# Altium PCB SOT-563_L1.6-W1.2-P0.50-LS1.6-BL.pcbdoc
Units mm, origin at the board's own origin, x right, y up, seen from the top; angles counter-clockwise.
Board outline 14.57 x 14.81 mm, 2 copper layers (Top Layer, Bottom Layer), stack 0 mm thick; 1 components, 0 nets, 6 pads, 0 vias.
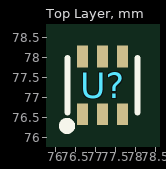
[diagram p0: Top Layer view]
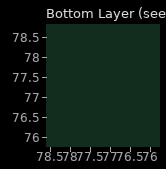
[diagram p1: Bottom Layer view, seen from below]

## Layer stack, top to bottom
Top Layer: signal copper (thickness not stored)
Bottom Layer: signal copper (thickness not stored)

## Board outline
84.415,69.85 69.85,69.85 69.85,84.661 84.415,84.661

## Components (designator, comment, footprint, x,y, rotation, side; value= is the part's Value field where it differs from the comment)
U? "" SOT-563_L1.6-W1.2-P0.50-LS1.6-BL 77.189,77.316 r0 top

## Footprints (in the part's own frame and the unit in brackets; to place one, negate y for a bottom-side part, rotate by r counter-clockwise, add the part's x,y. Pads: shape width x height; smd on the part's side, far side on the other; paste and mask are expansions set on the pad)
SOT-563_L1.6-W1.2-P0.50-LS1.6-BL [mm]
  rect 0.28x0.545 smd: 1(-0.5,-0.723) 2(0,-0.723) 3(0.5,-0.723) 4(0.5,0.723) 5(0,0.723) 6(-0.5,0.723)
  silkscreen extent -0.99,-1.12 0.88,0.68

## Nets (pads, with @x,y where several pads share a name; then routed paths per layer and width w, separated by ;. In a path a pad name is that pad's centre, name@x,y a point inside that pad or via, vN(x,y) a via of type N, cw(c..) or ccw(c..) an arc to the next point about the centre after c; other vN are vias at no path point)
pads on no net: U?.1 U?.2 U?.3 U?.4 U?.5 U?.6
